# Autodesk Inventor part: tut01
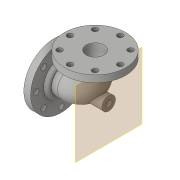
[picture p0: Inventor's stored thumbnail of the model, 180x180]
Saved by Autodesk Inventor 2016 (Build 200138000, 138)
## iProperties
Created: 2015-03
Part Number: tut01
Material: Generic
Document SubType Name: Modeling
Designer: Sandeep
Density: 1 g/cm^3
Appearance: Default
Author: Sandeep
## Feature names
1. Sweep1
2. Shell1
3. Extrusion1
4. Extrusion2
5. Extrusion3
6. Extrusion4
7. Fillet1
8. Extrusion5
9. Circular Pattern1
10. Extrusion6
11. Circular Pattern2
12. Extrusion7
13. Hole1
## Parameters: d1 = 35 mm, d2 = 35 mm, d4 = 97 mm, d5 = 0, d6 = 0, d7 = 16 mm, d8 = 225 mm, d9 = 25 mm, d10 = 0, d11 = 225 mm, d13 = 25 mm, d14 = 0, d15 = 86 mm, d16 = 22 mm, d17 = 0, d18 = 129 mm, d19 = 16 mm, d20 = 0, d21 = 16 mm, d22 = 185 mm, d23 = 20.5 mm, d24 = 0, d25 = 0, d27 = 360 deg, d29 = 185 mm, d30 = 20.5 mm, d31 = 16 mm, d32 = 0, d34 = 360 deg, d37 = 175 mm, d39 = 145 mm, d40 = 16 mm, d41 = 0, d45 = 6 mm, d46 = 24 mm, d47 = 28 mm, d48 = 90 deg, d49 = 8 mm, d50 = 118 deg
